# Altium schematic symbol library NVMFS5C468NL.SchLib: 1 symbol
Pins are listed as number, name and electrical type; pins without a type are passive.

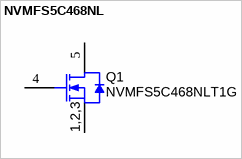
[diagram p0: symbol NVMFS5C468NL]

## NVMFS5C468NL
designator Q1, comment NVMFS5C468NLT1G
MOSFET, N-CH, 40 V, 37 A, AEC-Q101, DFN5 5x6mm; Manufacturer: ON Semiconductor; Alternate Manufacturer: None; U/M: EA; VdsMax_V: 40; ChType: N; Value: 40V; Value1: 0.0145 ohm; Rdson45_ohm: 0.0145; Value2: 4.5 nC; QgTyp_nC: 4.5; Vgs_V: 20; IdsMax_A: 27; SizeAreaWB_mm2: 58.2725; SizeArea_mm2: 31.6725; SizeX_mm: 5.15; SizeY_mm: 6.15; SizeZ_mm: 1; AEC Category: Q101; AEC Qualified: Y
footprint TRANS_DFN5
pins: 1 S, 2 S, 3 S, 4 G, 5 D, 6 D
